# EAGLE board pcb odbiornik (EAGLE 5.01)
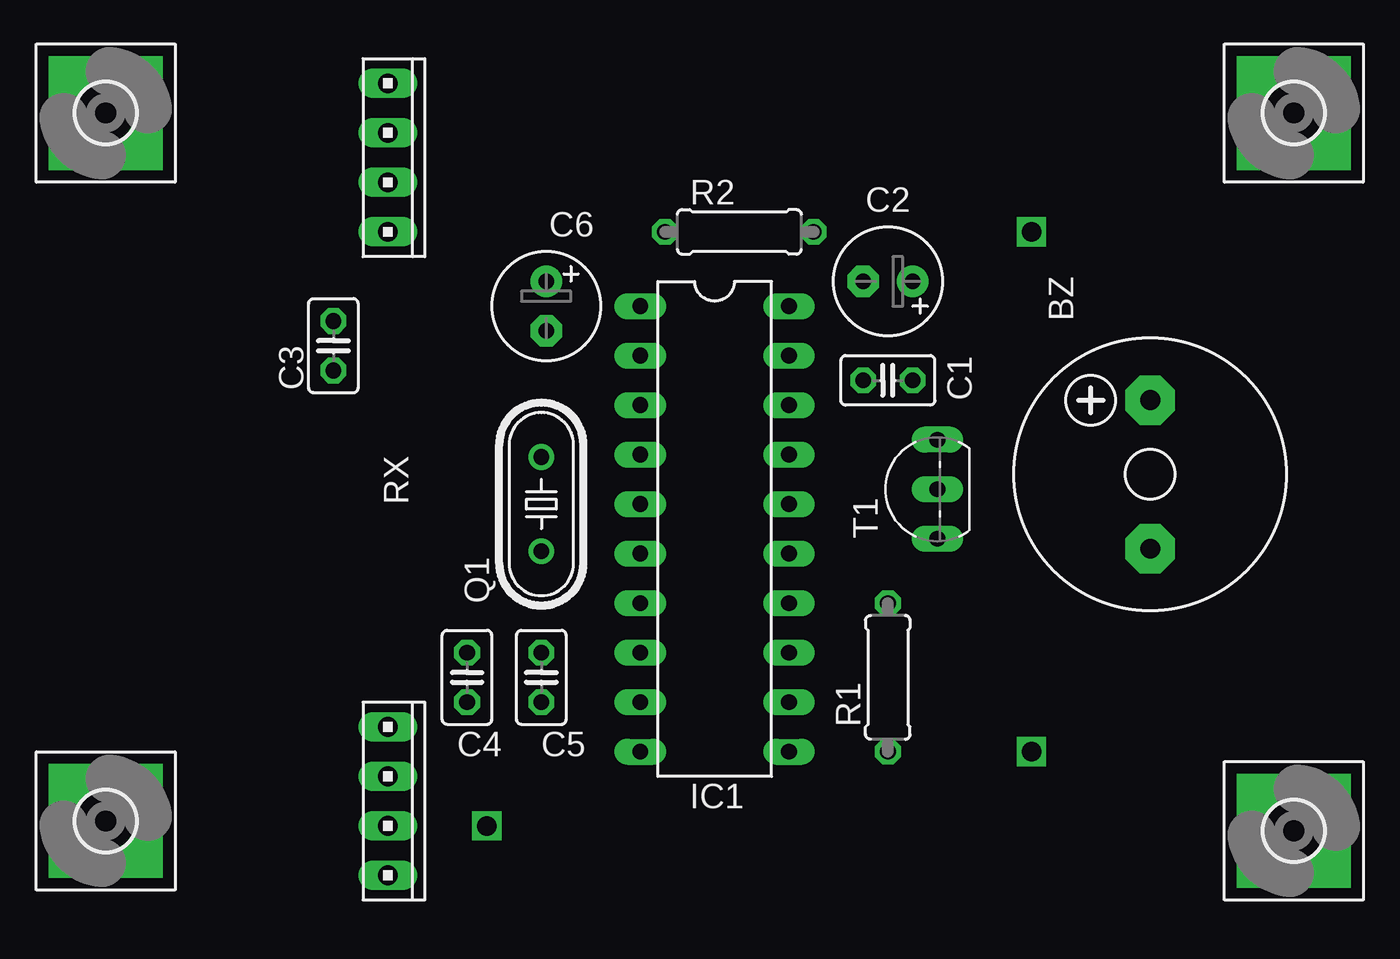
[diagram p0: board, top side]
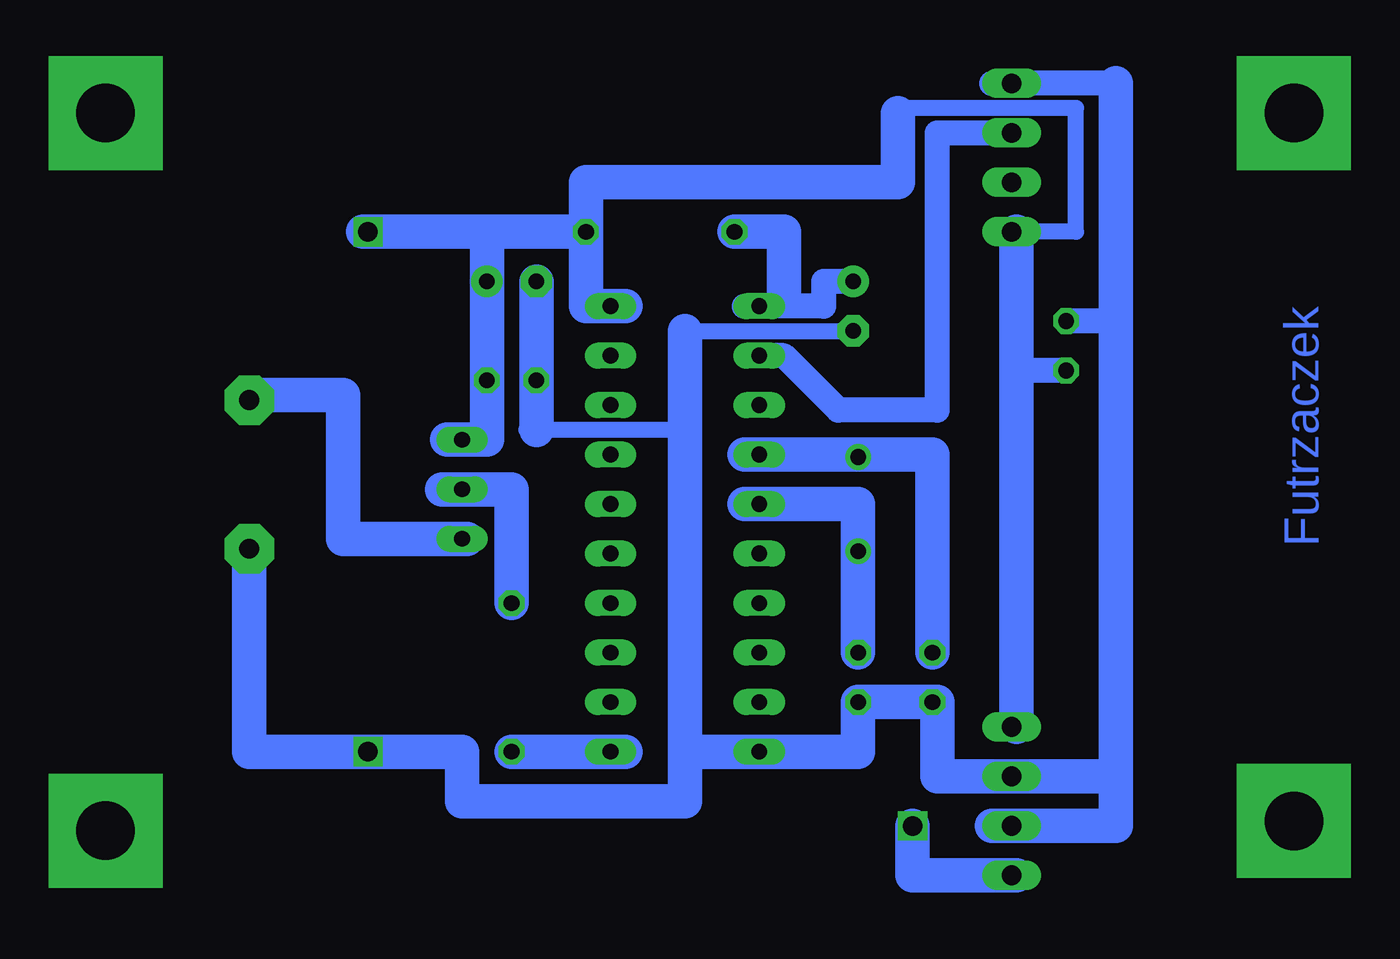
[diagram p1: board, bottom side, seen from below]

No outline drawn. Coordinates in mm, seen from the top.
Copper layers (1*16): Top 0.035mm / dielectric 1.5mm / Bottom 0.035mm
Design rules "default": minimum track width 10mil, minimum drill 24mil, track to track 8mil, track to pad 8mil, pad to pad 8mil, via to via 8mil, smd to smd 8mil, copper to edge 40mil, drill to drill 8mil, minimum pad ring 10mil, minimum via ring 8mil, stop-mask expansion 4mil, vias tented up to drill 0mil, thermal gap 10mil

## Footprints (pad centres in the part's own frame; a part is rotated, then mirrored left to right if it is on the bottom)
F/CM12P = drill 1.016 pad 2.54 octagon: + 3.81,0; - -3.81,0
C025-025X050 = drill 0.813 octagon: 1 -1.27,0; 2 1.27,0
E2,5-6 = drill 0.813 pad 1.6 round: + -1.27,0 | drill 0.813 pad 1.6 octagon: - 1.27,0
3,0-PAD-SQUARE = drill 3 pad 5.842 square: B3,0 0,0
DIL20 = drill 0.813 long: 1 -11.43,-3.81; 2 -8.89,-3.81; 3 -6.35,-3.81; 4 -3.81,-3.81; 5 -1.27,-3.81; 6 1.27,-3.81; 7 3.81,-3.81; 8 6.35,-3.81; 9 8.89,-3.81; 10 11.43,-3.81; 11 11.43,3.81; 12 8.89,3.81; 13 6.35,3.81; 14 3.81,3.81; 15 1.27,3.81; 16 -1.27,3.81; 17 -3.81,3.81; 18 -6.35,3.81; 19 -8.89,3.81; 20 -11.43,3.81
HC49/S = drill 0.813 round: 1 -2.413,0; 2 2.413,0
0207/7 = drill 0.813 octagon: 1 -3.81,0; 2 3.81,0
10X04MTA = drill 1.016 long: 1 3.81,0; 2 1.27,0; 3 -1.27,0; 4 -3.81,0
TO92-BCE = drill 0.813 long: B 2.54,0; C 0,0; E -2.54,0

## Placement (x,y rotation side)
BZ  [F/CM12P]  59.44,24.38 90 top
C1  [C025-025X050]  45.97,29.21 180 top
C2  [E2,5-6]  45.97,34.29 180 top
C3  [C025-025X050]  17.53,30.99 90 top
C4  [C025-025X050]  24.38,13.97 90 top
C5  [C025-025X050]  28.19,13.97 90 top
C6  [E2,5-6]  28.45,33.02 270 top
E$1  [3,0-PAD-SQUARE]  5.84,42.93 0 top
E$2  [3,0-PAD-SQUARE]  5.84,6.6 0 top
E$3  [3,0-PAD-SQUARE]  66.8,42.93 0 top
E$4  [3,0-PAD-SQUARE]  66.8,6.1 0 top
IC1  [DIL20]  37.08,21.59 270 top
Q1  [HC49/S]  28.19,22.86 90 top
R1  [0207/7]  45.97,13.97 90 top
R2  [0207/7]  38.35,36.83 0 top
RX  [10X04MTA]  20.32,7.62 270 top
T1  [TO92-BCE]  48.51,23.62 90 top
TX1  [10X04MTA]  20.32,40.64 270 top

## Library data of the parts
BZ = buzzer
C1-C6 R1 R2 = rcl
E$1-E$4 = holes
IC1 = 40xx
Q1 = crystal
RX TX1 = con-amp
T1 = transistor-pnp

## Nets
S$2: C2.+
S$3: C4.2
S$4: C5.2
S$6: C4.1 C5.1 C6.-
S$10: IC1.11 R1.1
S$12: C6.+
S$13: C3.2
S$14: C3.1
S$16: IC1.2
S$17: TX1.1
S$19: R1.2

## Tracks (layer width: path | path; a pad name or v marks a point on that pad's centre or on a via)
S$1
  Bottom 1.778: 34.54,36.83 32,36.83 32,33.53
S$2
  Bottom 1.778: 40.13,33.02 42.16,33.02 42.16,36.83 | 42.16,36.83 47.24,36.83 | 42.16,36.83 42.16,39.37 26.16,39.37 26.16,42.93 | 47.24,36.83 C2.+ 47.24,29.21 | 47.24,36.83 53.59,36.83
S$3
  Bottom 1.778: 34.04,25.4 24.38,25.4 C4.2
S$4
  Bottom 1.778: 34.04,22.86 28.19,22.86 C5.2
S$5  (via drill 1)
  Bottom 1.778: 20.07,3.81 25.4,3.81 v25.4,6.35
S$6
  Bottom 0.813: 37.08,31.75 C6.-
  Bottom 1.778: 53.59,10.16 48.51,10.16 48.51,7.62 37.08,7.62 37.08,10.16 | 37.08,10.16 37.08,31.75 | 33.27,10.16 34.54,10.16 | 33.27,10.16 37.08,10.16 | 33.27,10.16 28.19,10.16 C5.1 C4.1
S$7  (via drill 1)
  other vias: 53.34,36.83
S$8
  Bottom 1.27: 14.99,44.45 21.34,44.45
  Bottom 1.778: 14.99,8.89 14.99,44.45 | 14.99,8.89 20.07,8.89 | 20.07,8.89 21.34,8.89 | 21.34,6.35 14.99,6.35 14.99,8.89 | 20.07,8.89 24.13,8.89 24.13,12.7
S$9
  Bottom 1.778: 20.07,11.43 20.07,36.83
S$10
  Bottom 1.778: R1.1 IC1.11 40.13,10.16
S$11
  Bottom 0.813: 37.34,26.67 44.7,26.67 45.21,26.67
  Bottom 1.778: 44.7,26.67 44.7,34.29
S$12
  Bottom 1.27: 34.04,33.02 29.97,33.02 29.97,34.29 C6.+
S$13
  Bottom 1.27: 15.24,32.26 C3.2
S$14
  Bottom 1.27: C3.1 19.81,29.72
S$16
  Bottom 1.27: IC1.2 32,30.48 29.21,27.69 24.13,27.69 24.13,41.91 19.81,41.91
S$17
  Bottom 0.813: 26.16,43.18 17.02,43.18 17.02,36.83 TX1.1
S$18
  Bottom 1.778: 49.28,26.16 47.24,26.16 47.24,29.46
S$19
  Bottom 1.778: 49.53,23.62 45.97,23.62 R1.2
S$20
  Bottom 1.778: 48.26,21.08 54.61,21.08 54.61,28.45 59.44,28.45
S$21  (via drill 1)
  Bottom 1.778: 59.44,20.32 59.44,10.16 v53.34,10.16

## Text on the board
Bottom: Futrzaczek
tValues: 1 | + | 4 | - | 5 | ANT | 8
